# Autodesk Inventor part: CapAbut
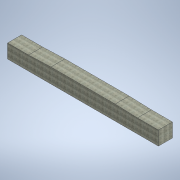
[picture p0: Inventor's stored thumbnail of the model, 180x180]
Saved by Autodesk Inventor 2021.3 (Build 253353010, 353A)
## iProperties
Created: 2021-11
Part Number: CapAbut
Material: Concrete, Cast-in-Place, Gray
Document SubType Name: Modeling
Designer: u1426
Density: 2.40731 g/cm^3
Appearance: Flat - Gray 1
Author: u1426
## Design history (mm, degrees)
sketch "Sketch1"
  geometry: L1 (0, 0)-(-5486.4, 0); L2 (-5486.4, 0)-(-5486.4, 1016); L3 (0, 0)-(5486.4, 0); L4 (5486.4, 0)-(5486.4, 1016); L5 (5486.4, 1016)-(3962.4, 1016); L6 (-5486.4, 1016)-(-3962.4, 1016); L7 (-3962.4, 1016)-(-2336.8, 1076.96); L8 (-2336.8, 1076.96)-(2336.8, 1076.96); L9 (2336.8, 1076.96)-(3962.4, 1016)
  constraints: 18 end point, 4 horizontal, 3 perpendicular
  dimensions: "d0" = 5486.4 distance of L1.start L1.end; "d1" = 1016 distance of L1.end L2.end; "d2" = 5486.4 distance of L1.start L3.end; "d3" = 1016 distance of L3.end L4.end; "d4" = 1524 distance of L4.end L5.end; "d5" = 1524 distance of L2.end L6.end; "d6" = 1625.6 horizontal distance of L8.end L5.end; "d7" = 1625.6 horizontal distance of L6.end L7.end; "d8" = 4673.6 distance of L7.end L8.end (derived); "d9" = 2336.8 horizontal distance of L7.end L1.start (derived); "d10" = 60.96 vertical distance of L6.end L7.end
extrude "Extrusion1" new body sketch "Sketch1" distance "d11" = 1016; taper "d12" = 0 deg
sketch "Sketch2"
  geometry: L1 (0, 0)-(10972.8, 0) reference; 5 further points
  dimensions: "d20" = 3149.6 distance of point (3911.6, -508) point (762, -508); "d21" = 3149.6 distance of point (10210.8, -508) point (7061.2, -508); "d22" = 508 distance from line of L1 point (10210.8, -508); "d23" = 508 distance from line of point (7061.2, -508) L1; "d24" = 508 distance from line of point (3911.6, -508) L1; "d25" = 508 distance from line of point (762, -508) L1; "d26" = 1574.8 horizontal distance of point (5486.4, 0) point (3911.6, -508); "d27" = 1574.8 horizontal distance of point (5486.4, 0) point (7061.2, -508)
hole "Hole1" sketch "Sketch2" at (762, -508), (3911.6, -508), (7061.2, -508), (10210.8, -508) diameter "d13" = 406.4; stored, may be unused: countersink angle "d17" = 82 deg, drill point angle "d19" = 0 deg; dims "d14" = 19.05, "d15" = 9.525, "d16" = 6.35, "d18" = 508
body "Solid1"
